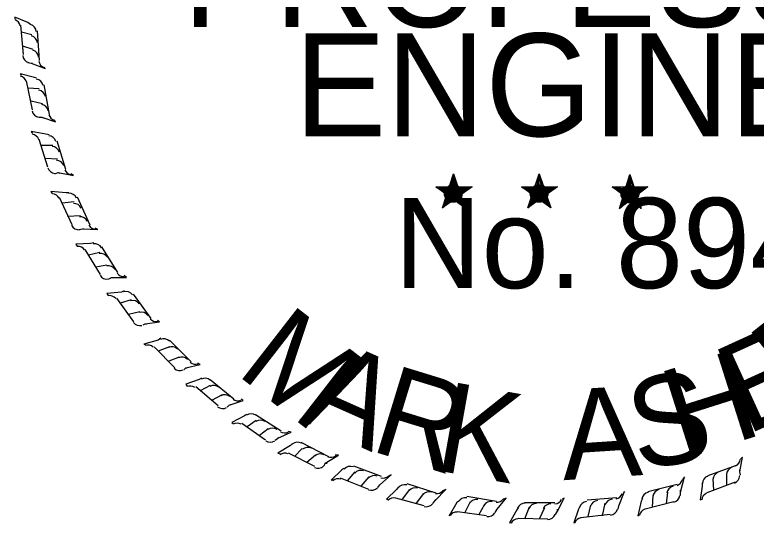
# Model space of a CAD drawing. Extents: x 1369528 to 1373075, y 373809 to 376031.
# Drawn here: x 1372616.4 to 1372751.6, y 373959.4 to 374052.1 of the extents above; entities that cross this region are included whole.
import ezdxf

# ---------------------------------------------------------------- set-up
doc = ezdxf.new("R2010")
doc.units = 0
doc.layers.add('R_Border Notes', color=7, linetype='Continuous')

msp = doc.modelspace()

# ---------------------------------------------------------------- linework, layer by layer
at = {"layer": 'R_Border Notes'}
for p, q in [((1372618.79, 374050.76), (1372616.39, 374051.72)), ((1372616.39, 374051.72), (1372616.39, 374051.36)), ((1372617.95, 374044.88), (1372617.47, 374050.28)), ((1372619.27, 374050.4), (1372618.79, 374050.76)), ((1372619.51, 374048.48), (1372617.59, 374048.96)), ((1372620.47, 374049.2), (1372620.83, 374043.8)), ((1372619.75, 374045.84), (1372617.83, 374046.44)), ((1372618.79, 374043.44), (1372619.39, 374043.32)), ((1372619.39, 374043.32), (1372621.91, 374042.36)), ((1372619.39, 374043.32), (1372619.63, 374043.32)), ((1372621.91, 374042.36), (1372621.79, 374042.6)), ((1372619.99, 374040.68), (1372617.35, 374041.4)), ((1372617.35, 374041.4), (1372617.59, 374041.16)), ((1372620.35, 374040.56), (1372619.99, 374040.68)), ((1372619.63, 374034.8), (1372618.55, 374040.08)), ((1372621.67, 374039.36), (1372622.63, 374033.96)), ((1372620.83, 374038.64), (1372618.79, 374038.76)), ((1372621.43, 374035.88), (1372619.39, 374036.36)), ((1372620.83, 374033.48), (1372621.31, 374033.48)), ((1372621.31, 374033.48), (1372623.83, 374032.64)), ((1372621.31, 374033.48), (1372621.55, 374033.36)), ((1372623.83, 374032.64), (1372623.59, 374033)), ((1372622.03, 374030.36), (1372619.39, 374030.84)), ((1372619.39, 374030.84), (1372619.63, 374030.48)), ((1372622.39, 374024.36), (1372620.83, 374029.4)), ((1372622.63, 374030.24), (1372622.03, 374030.36)), ((1372623.35, 374028.32), (1372621.19, 374028.32)), ((1372624.07, 374029.16), (1372625.63, 374024)), ((1372624.19, 374025.8), (1372621.91, 374025.92)), ((1372623.71, 374023.16), (1372624.31, 374023.4)), ((1372624.31, 374023.4), (1372627.07, 374022.8)), ((1372624.31, 374023.4), (1372624.55, 374023.28)), ((1372627.07, 374022.8), (1372626.59, 374023.16)), ((1372696.43, 374023.16), (1372695.83, 374020.76)), ((1372696.43, 374023.16), (1372696.07, 374020.76)), ((1372696.43, 374023.16), (1372696.19, 374020.76)), ((1372696.43, 374019.68), (1372696.43, 374023.16)), ((1372696.43, 374023.16), (1372697.03, 374020.76)), ((1372696.43, 374023.16), (1372696.91, 374020.76)), ((1372696.43, 374023.16), (1372696.67, 374020.76)), ((1372712.03, 374023.16), (1372711.55, 374020.76)), ((1372712.03, 374023.16), (1372711.79, 374020.76)), ((1372712.03, 374023.16), (1372711.91, 374020.76)), ((1372712.03, 374019.68), (1372712.03, 374023.16)), ((1372712.03, 374023.16), (1372712.63, 374020.76)), ((1372712.03, 374023.16), (1372712.51, 374020.76)), ((1372712.03, 374023.16), (1372712.39, 374020.76)), ((1372728.59, 374023.04), (1372728.11, 374020.76)), ((1372728.59, 374023.04), (1372728.23, 374020.76)), ((1372728.59, 374019.56), (1372728.59, 374023.04)), ((1372728.59, 374023.04), (1372729.19, 374020.76)), ((1372728.59, 374023.04), (1372729.19, 374020.76)), ((1372728.59, 374023.04), (1372728.83, 374020.76)), ((1372728.59, 374023.04), (1372728.59, 374020.76)), ((1372625.75, 374019.68), (1372622.99, 374019.92)), ((1372622.99, 374019.92), (1372623.23, 374019.56)), ((1372693.19, 374020.76), (1372696.43, 374019.68)), ((1372693.19, 374020.76), (1372695.59, 374020.52)), ((1372693.19, 374020.76), (1372695.59, 374020.28)), ((1372693.19, 374020.76), (1372695.47, 374020.16)), ((1372693.19, 374020.76), (1372695.47, 374019.8)), ((1372693.19, 374020.76), (1372695.35, 374019.56)), ((1372693.19, 374020.76), (1372695.35, 374019.44)), ((1372699.79, 374020.76), (1372696.43, 374019.68)), ((1372699.79, 374020.76), (1372696.79, 374020.52)), ((1372699.79, 374020.76), (1372697.03, 374020.28)), ((1372699.79, 374020.76), (1372697.03, 374020.16)), ((1372699.79, 374020.76), (1372697.63, 374019.92)), ((1372699.79, 374020.76), (1372697.75, 374019.8)), ((1372699.79, 374020.76), (1372697.99, 374019.68)), ((1372708.79, 374020.76), (1372712.03, 374019.68)), ((1372708.79, 374020.76), (1372711.19, 374020.52)), ((1372708.79, 374020.76), (1372711.19, 374020.28)), ((1372708.79, 374020.76), (1372711.19, 374020.16)), ((1372708.79, 374020.76), (1372711.07, 374019.8)), ((1372708.79, 374020.76), (1372711.07, 374019.56)), ((1372708.79, 374020.76), (1372711.07, 374019.44)), ((1372715.39, 374020.76), (1372712.03, 374019.68)), ((1372715.39, 374020.76), (1372712.39, 374020.52)), ((1372715.39, 374020.76), (1372712.63, 374020.28)), ((1372715.39, 374020.76), (1372712.63, 374020.16)), ((1372715.39, 374020.76), (1372713.23, 374019.92)), ((1372715.39, 374020.76), (1372713.47, 374019.8)), ((1372715.39, 374020.76), (1372713.59, 374019.68)), ((1372725.35, 374020.76), (1372728.59, 374019.56)), ((1372725.35, 374020.76), (1372727.75, 374020.4)), ((1372725.35, 374020.76), (1372727.75, 374020.16)), ((1372725.35, 374020.76), (1372727.63, 374020.16)), ((1372725.35, 374020.76), (1372727.63, 374019.68)), ((1372725.35, 374020.76), (1372727.63, 374019.56)), ((1372725.35, 374020.76), (1372727.63, 374019.32)), ((1372731.83, 374020.76), (1372728.59, 374019.56)), ((1372731.83, 374020.76), (1372729.07, 374020.4)), ((1372731.83, 374020.76), (1372729.19, 374020.16)), ((1372731.83, 374020.76), (1372729.19, 374020.04)), ((1372731.83, 374020.76), (1372729.79, 374019.8)), ((1372731.83, 374020.76), (1372730.03, 374019.68)), ((1372731.83, 374020.76), (1372730.15, 374019.56)), ((1372626.83, 374013.8), (1372624.55, 374018.84)), ((1372626.23, 374019.68), (1372625.75, 374019.68)), ((1372627.79, 374018.96), (1372630.07, 374013.8)), ((1372694.39, 374016.92), (1372696.43, 374019.68)), ((1372694.39, 374016.92), (1372695.47, 374019.56)), ((1372694.39, 374016.92), (1372695.59, 374019.2)), ((1372694.39, 374016.92), (1372695.71, 374019.08)), ((1372694.39, 374016.92), (1372696.07, 374018.96)), ((1372694.39, 374016.92), (1372696.43, 374018.96)), ((1372694.39, 374016.92), (1372696.43, 374018.72)), ((1372698.47, 374016.92), (1372696.43, 374019.68)), ((1372698.47, 374016.92), (1372696.43, 374018.96)), ((1372698.47, 374016.92), (1372696.43, 374018.6)), ((1372698.47, 374016.92), (1372696.79, 374018.96)), ((1372698.47, 374016.92), (1372697.03, 374019.2)), ((1372698.47, 374016.92), (1372697.15, 374019.56)), ((1372698.47, 374016.92), (1372697.39, 374019.68)), ((1372709.99, 374016.92), (1372712.03, 374019.68)), ((1372709.99, 374016.92), (1372711.19, 374019.56)), ((1372709.99, 374016.92), (1372711.19, 374019.2)), ((1372709.99, 374016.92), (1372711.43, 374019.08)), ((1372709.99, 374016.92), (1372711.79, 374018.96)), ((1372709.99, 374016.92), (1372712.03, 374018.96)), ((1372709.99, 374016.92), (1372712.15, 374018.72)), ((1372714.19, 374016.92), (1372712.03, 374019.68)), ((1372714.19, 374016.92), (1372712.03, 374018.96)), ((1372714.19, 374016.92), (1372712.03, 374018.6)), ((1372714.19, 374016.92), (1372712.39, 374018.96)), ((1372714.19, 374016.92), (1372712.63, 374019.2)), ((1372714.19, 374016.92), (1372712.87, 374019.56)), ((1372714.19, 374016.92), (1372712.99, 374019.68)), ((1372726.67, 374016.8), (1372728.59, 374019.56)), ((1372726.67, 374016.8), (1372727.63, 374019.44)), ((1372726.67, 374016.8), (1372727.87, 374019.08)), ((1372726.67, 374016.8), (1372727.99, 374018.96)), ((1372726.67, 374016.8), (1372728.23, 374018.84)), ((1372726.67, 374016.8), (1372728.59, 374018.84)), ((1372726.67, 374016.8), (1372728.71, 374018.6)), ((1372730.63, 374016.8), (1372728.59, 374019.56)), ((1372730.63, 374016.8), (1372728.59, 374018.84)), ((1372730.63, 374016.8), (1372728.59, 374018.6)), ((1372730.63, 374016.8), (1372729.07, 374018.84)), ((1372730.63, 374016.8), (1372729.31, 374019.56)), ((1372730.63, 374016.8), (1372729.31, 374019.08)), ((1372730.63, 374016.8), (1372729.55, 374019.56)), ((1372627.19, 374018), (1372625.03, 374017.76)), ((1372628.39, 374015.48), (1372625.99, 374015.36)), ((1372628.15, 374012.96), (1372628.75, 374013.08)), ((1372628.75, 374013.08), (1372631.51, 374012.96)), ((1372628.75, 374013.08), (1372628.99, 374013.08)), ((1372631.51, 374012.96), (1372631.03, 374013.2)), ((1372630.19, 374010.44), (1372627.55, 374010.32)), ((1372630.79, 374010.56), (1372630.19, 374010.44)), ((1372627.55, 374010.32), (1372627.79, 374009.96)), ((1372631.99, 374004.8), (1372629.23, 374009.36)), ((1372632.23, 374009.84), (1372635.11, 374005.16)), ((1372631.87, 374008.76), (1372629.83, 374008.28)), ((1372633.19, 374006.48), (1372631.15, 374006.12)), ((1372633.55, 374003.96), (1372634.03, 374004.2)), ((1372634.03, 374004.2), (1372636.79, 374004.2)), ((1372634.03, 374004.2), (1372634.39, 374004.2)), ((1372636.79, 374004.2), (1372636.31, 374004.56)), ((1372635.83, 374001.56), (1372633.19, 374001.32)), ((1372633.19, 374001.32), (1372633.43, 374000.96)), ((1372636.31, 374001.8), (1372635.83, 374001.56)), ((1372637.99, 374001.2), (1372641.23, 373996.76)), ((1372638.11, 373996.16), (1372634.99, 374000.48)), ((1372637.63, 374000.12), (1372635.59, 373999.52)), ((1372639.19, 373997.96), (1372637.15, 373997.48)), ((1372639.79, 373995.56), (1372640.15, 373995.8)), ((1372640.15, 373995.8), (1372642.79, 373996.16)), ((1372640.15, 373995.8), (1372640.39, 373995.8)), ((1372642.79, 373996.16), (1372642.43, 373996.4)), ((1372642.55, 373992.8), (1372639.91, 373992.08)), ((1372643.03, 373993.16), (1372642.55, 373992.8)), ((1372644.59, 373992.8), (1372648.55, 373988.84)), ((1372639.91, 373992.08), (1372640.27, 373991.96)), ((1372645.55, 373987.76), (1372641.83, 373991.6)), ((1372644.59, 373991.6), (1372642.55, 373990.76)), ((1372646.39, 373989.68), (1372644.47, 373988.96)), ((1372647.23, 373987.4), (1372647.59, 373987.76)), ((1372647.59, 373987.76), (1372650.23, 373988.36)), ((1372647.59, 373987.76), (1372647.83, 373987.76)), ((1372650.23, 373988.36), (1372649.75, 373988.6)), ((1372649.99, 373985.6), (1372647.59, 373984.76)), ((1372647.59, 373984.76), (1372647.83, 373984.4)), ((1372650.47, 373985.84), (1372649.99, 373985.6)), ((1372652.03, 373985.6), (1372656.35, 373982.12)), ((1372653.47, 373980.8), (1372649.39, 373984.28)), ((1372652.03, 373984.52), (1372650.23, 373983.56)), ((1372654.19, 373982.84), (1372652.27, 373981.76)), ((1372658.03, 373981.76), (1372657.67, 373982)), ((1372655.15, 373980.56), (1372655.51, 373980.92)), ((1372655.51, 373980.92), (1372658.03, 373981.76)), ((1372655.51, 373980.92), (1372655.75, 373981.04)), ((1372658.27, 373979), (1372655.99, 373977.8)), ((1372658.63, 373979.24), (1372658.27, 373979)), ((1372660.43, 373978.16), (1372658.75, 373976.96)), ((1372660.31, 373979.24), (1372664.99, 373976.24)), ((1372655.99, 373977.8), (1372656.23, 373977.56)), ((1372662.11, 373974.56), (1372657.79, 373977.56)), ((1372662.59, 373976.6), (1372661.03, 373975.4)), ((1372664.39, 373974.92), (1372666.79, 373976)), ((1372666.79, 373976), (1372666.31, 373976.12)), ((1372663.91, 373974.56), (1372664.39, 373974.92)), ((1372664.39, 373974.92), (1372664.51, 373975.04)), ((1372667.03, 373973.96), (1372666.67, 373973.6)), ((1372668.59, 373974.2), (1372673.63, 373971.56)), ((1372666.67, 373973.6), (1372664.39, 373972.16)), ((1372668.83, 373973), (1372667.39, 373971.56)), ((1372664.39, 373972.16), (1372664.87, 373972.04)), ((1372671.11, 373969.76), (1372666.31, 373972.16)), ((1372671.23, 373971.8), (1372669.67, 373970.48)), ((1372673.03, 373970.36), (1372675.43, 373971.8)), ((1372675.43, 373971.8), (1372674.83, 373971.8)), ((1372748.63, 373968.8), (1372749.11, 373971.44)), ((1372749.11, 373971.44), (1372748.75, 373971.08)), ((1372672.79, 373969.88), (1372673.03, 373970.36)), ((1372673.03, 373970.36), (1372673.39, 373970.36)), ((1372678.19, 373969.88), (1372683.23, 373967.96)), ((1372742.87, 373968.08), (1372748.03, 373970)), ((1372676.03, 373969.16), (1372674.11, 373967.24)), ((1372676.39, 373969.4), (1372676.03, 373969.16)), ((1372678.43, 373968.8), (1372676.99, 373967.12)), ((1372748.63, 373968.8), (1372748.63, 373969.16)), ((1372748.75, 373968.2), (1372748.63, 373968.8)), ((1372674.11, 373967.24), (1372674.59, 373967.36)), ((1372680.95, 373965.56), (1372675.79, 373967.6)), ((1372680.95, 373967.84), (1372679.51, 373966.16)), ((1372682.99, 373966.4), (1372685.03, 373968.2)), ((1372685.03, 373968.2), (1372684.55, 373967.96)), ((1372737.83, 373965.08), (1372738.55, 373967.84)), ((1372738.55, 373967.84), (1372738.19, 373967.36)), ((1372743.71, 373967.48), (1372743.83, 373965.44)), ((1372746.23, 373968.44), (1372746.23, 373966.28)), ((1372682.63, 373965.92), (1372682.99, 373966.4)), ((1372682.99, 373966.4), (1372683.11, 373966.52)), ((1372686.35, 373966.04), (1372685.99, 373965.56)), ((1372687.91, 373966.64), (1372693.19, 373964.96)), ((1372731.83, 373965.2), (1372737.23, 373966.52)), ((1372741.79, 373966.16), (1372741.43, 373963.64)), ((1372741.79, 373966.76), (1372741.79, 373966.16)), ((1372747.79, 373966.88), (1372742.63, 373964.96)), ((1372685.99, 373965.56), (1372684.19, 373963.76)), ((1372688.39, 373965.56), (1372687.07, 373963.76)), ((1372690.91, 373964.84), (1372689.59, 373963.04)), ((1372693.07, 373963.52), (1372694.99, 373965.56)), ((1372694.99, 373965.56), (1372694.39, 373965.32)), ((1372726.55, 373962.56), (1372727.63, 373965.2)), ((1372727.63, 373965.2), (1372727.27, 373964.84)), ((1372732.79, 373964.48), (1372732.67, 373962.32)), ((1372735.43, 373965.08), (1372735.19, 373962.92)), ((1372737.83, 373965.08), (1372737.83, 373965.44)), ((1372737.83, 373964.48), (1372737.83, 373965.08)), ((1372684.19, 373963.76), (1372684.43, 373963.76)), ((1372691.03, 373962.56), (1372685.87, 373964)), ((1372692.71, 373963.04), (1372693.07, 373963.52)), ((1372693.07, 373963.52), (1372693.19, 373963.76)), ((1372697.03, 373963.16), (1372695.59, 373960.76)), ((1372697.39, 373963.4), (1372697.03, 373963.16)), ((1372699.43, 373963.28), (1372698.47, 373961.36)), ((1372698.83, 373964.36), (1372704.23, 373963.4)), ((1372704.35, 373961.96), (1372706.03, 373964)), ((1372706.03, 373964), (1372705.55, 373963.76)), ((1372709.39, 373963.16), (1372714.91, 373963.16)), ((1372715.39, 373961.6), (1372716.59, 373964)), ((1372716.59, 373964), (1372716.23, 373963.76)), ((1372720.79, 373963.64), (1372726.19, 373964.12)), ((1372730.63, 373963.4), (1372730.03, 373960.76)), ((1372730.87, 373963.88), (1372730.63, 373963.4)), ((1372736.63, 373963.28), (1372731.35, 373961.96)), ((1372741.43, 373963.64), (1372741.79, 373963.76)), ((1372702.07, 373962.8), (1372700.99, 373960.88)), ((1372703.99, 373961.36), (1372704.35, 373961.96)), ((1372704.35, 373961.96), (1372704.47, 373962.08)), ((1372707.95, 373961.84), (1372706.63, 373959.44)), ((1372708.19, 373962.2), (1372707.95, 373961.84)), ((1372710.23, 373962.32), (1372709.39, 373960.16)), ((1372712.99, 373962.2), (1372712.03, 373960.16)), ((1372715.39, 373961.6), (1372715.39, 373961.96)), ((1372719.23, 373961.96), (1372718.39, 373959.44)), ((1372719.47, 373962.44), (1372719.23, 373961.96)), ((1372721.39, 373962.68), (1372720.91, 373960.64)), ((1372724.03, 373963.04), (1372723.55, 373960.76)), ((1372726.43, 373961.96), (1372726.55, 373962.56)), ((1372726.55, 373962.56), (1372726.67, 373962.8)), ((1372695.59, 373960.76), (1372695.83, 373961)), ((1372702.43, 373960.76), (1372697.15, 373961.48)), ((1372715.03, 373961), (1372715.39, 373961.6)), ((1372724.99, 373961), (1372719.59, 373960.4)), ((1372730.03, 373960.76), (1372730.39, 373961)), ((1372706.63, 373959.44), (1372706.99, 373959.56)), ((1372713.59, 373960.16), (1372708.19, 373960.28)), ((1372718.39, 373959.44), (1372718.63, 373959.56))]:
    msp.add_line(p, q, dxfattribs=at)
for points in [[(1372696.43, 374023.16), (1372698.47, 374016.92), (1372693.19, 374020.76), (1372699.79, 374020.76), (1372694.39, 374016.92), (1372696.43, 374023.16)], [(1372712.03, 374023.16), (1372714.19, 374016.92), (1372708.79, 374020.76), (1372715.39, 374020.76), (1372709.99, 374016.92), (1372712.03, 374023.16)], [(1372728.59, 374023.04), (1372730.63, 374016.8), (1372725.35, 374020.76), (1372731.83, 374020.76), (1372726.67, 374016.8), (1372728.59, 374023.04)]]:
    msp.add_lwpolyline(points, dxfattribs=at)
for centre, radius in [((1372696.37, 374019.56), 1.61), ((1372696.37, 374019.56), 1.46), ((1372696.37, 374019.56), 1.36), ((1372696.37, 374019.56), 1.24), ((1372696.37, 374019.56), 1.09), ((1372696.37, 374019.56), 1.01), ((1372696.37, 374019.56), 0.929), ((1372696.37, 374019.56), 0.8), ((1372696.37, 374019.56), 0.701), ((1372696.37, 374019.56), 0.583), ((1372696.37, 374019.56), 0.464), ((1372696.37, 374019.56), 0.346), ((1372696.37, 374019.56), 0.278), ((1372712.02, 374019.56), 1.61), ((1372712.02, 374019.56), 1.46), ((1372712.02, 374019.56), 1.36), ((1372712.02, 374019.56), 1.24), ((1372712.02, 374019.56), 1.09), ((1372712.02, 374019.56), 1.01), ((1372712.02, 374019.56), 0.929), ((1372712.02, 374019.56), 0.8), ((1372712.02, 374019.56), 0.701), ((1372712.02, 374019.56), 0.583), ((1372712.02, 374019.56), 0.464), ((1372712.02, 374019.56), 0.346), ((1372712.02, 374019.56), 0.278), ((1372728.58, 374019.45), 1.61), ((1372728.58, 374019.45), 1.46), ((1372728.58, 374019.45), 1.36), ((1372728.58, 374019.45), 1.24), ((1372728.58, 374019.45), 1.09), ((1372728.58, 374019.45), 1.01), ((1372728.58, 374019.45), 0.929), ((1372728.58, 374019.45), 0.8), ((1372728.58, 374019.45), 0.701), ((1372728.58, 374019.45), 0.583), ((1372728.58, 374019.45), 0.464), ((1372696.37, 374019.56), 0.135), ((1372712.02, 374019.56), 0.135), ((1372728.58, 374019.45), 0.346), ((1372728.58, 374019.45), 0.278), ((1372728.58, 374019.45), 0.135)]:
    msp.add_circle(centre, radius, dxfattribs=at)
for centre, start, end in [((1372615.89, 374049.88), 9.4933, 68.2812), ((1372618.84, 374048.95), 5.2325, 73.6065), ((1372619.03, 374046.9), 5.2325, 73.6065), ((1372619.26, 374044.27), 5.2325, 73.6065), ((1372619.3, 374044.84), 185.2325, 253.6065), ((1372622.24, 374043.91), 189.4933, 248.2812), ((1372617.06, 374039.55), 15.7912, 74.579), ((1372620.09, 374038.95), 11.5304, 79.9044), ((1372620.51, 374036.94), 11.5304, 79.9044), ((1372621.03, 374034.35), 11.5304, 79.9044), ((1372621, 374034.92), 191.5304, 259.9044), ((1372624.03, 374034.32), 195.7912, 254.579), ((1372619.39, 374028.87), 22.0938, 80.8817), ((1372622.47, 374028.6), 17.8331, 86.207), ((1372623.11, 374026.65), 17.8331, 86.207), ((1372623.91, 374024.13), 17.8331, 86.207), ((1372623.81, 374024.7), 197.8331, 266.207), ((1372626.89, 374024.43), 202.0938, 260.8817), ((1372623.2, 374017.99), 29.1451, 87.9329), ((1372626.29, 374018.1), 24.8843, 93.2583), ((1372627.16, 374016.24), 24.8843, 93.2583), ((1372628.26, 374013.84), 24.8843, 93.2583), ((1372628.1, 374014.39), 204.8843, 273.2583), ((1372631.19, 374014.5), 209.1451, 267.9329), ((1372627.91, 374008.4), 36.0034, 94.7913), ((1372630.96, 374008.88), 31.7427, 100.1166), ((1372632.04, 374007.13), 31.7427, 100.1166), ((1372633.43, 374004.88), 31.7427, 100.1166), ((1372636.25, 374005.89), 216.0034, 274.7913), ((1372633.2, 374005.41), 211.7427, 280.1166), ((1372633.67, 373999.44), 40.9505, 99.7383), ((1372636.67, 374000.18), 36.6897, 105.0637), ((1372637.9, 373998.54), 36.6897, 105.0637), ((1372639.47, 373996.41), 36.6897, 105.0637), ((1372639.2, 373996.92), 216.6897, 285.0637), ((1372642.2, 373997.66), 220.9505, 279.7383), ((1372643.54, 373991.57), 44.9655, 113.3394), ((1372640.67, 373990.4), 49.2262, 108.0141), ((1372644.99, 373990.12), 44.9655, 113.3394), ((1372646.85, 373988.24), 44.9655, 113.3394), ((1372649.37, 373989.87), 229.2262, 288.0141), ((1372646.51, 373988.71), 224.9655, 293.3394), ((1372651.09, 373984.37), 50.1902, 118.5642), ((1372648.35, 373982.95), 54.451, 113.2388), ((1372652.67, 373983.06), 50.1902, 118.5642), ((1372654.7, 373981.36), 50.1902, 118.5642), ((1372657.06, 373983.21), 234.451, 293.2388), ((1372654.32, 373981.79), 230.1902, 298.5642), ((1372659.5, 373977.88), 56.1736, 124.5476), ((1372661.21, 373976.74), 56.1736, 124.5476), ((1372656.92, 373976.18), 60.4344, 119.2222), ((1372663.4, 373975.26), 56.1736, 124.5476), ((1372665.56, 373977.35), 240.4344, 299.2222), ((1372662.98, 373975.65), 236.1736, 304.5476), ((1372667.99, 373972.69), 63.0708, 131.4448), ((1372669.82, 373971.77), 63.0708, 131.4448), ((1372665.63, 373970.7), 67.3316, 126.1194), ((1372672.17, 373970.56), 63.0708, 131.4448), ((1372674.06, 373972.89), 247.3316, 306.1194), ((1372747.26, 373971.2), 294.7331, 353.521), ((1372671.7, 373970.9), 243.0708, 311.4448), ((1372677.56, 373968.28), 69.0955, 137.4695), ((1372679.48, 373967.55), 69.0955, 137.4695), ((1372745.22, 373967.32), 110.4724, 178.8463), ((1372747.7, 373968.23), 110.4724, 178.8463), ((1372675.42, 373966.04), 73.3563, 132.1441), ((1372681.95, 373966.6), 69.0955, 137.4695), ((1372683.58, 373969.11), 253.3563, 312.1441), ((1372736.72, 373967.71), 288.1674, 346.9552), ((1372743.3, 373966.6), 110.4724, 178.8463), ((1372747.13, 373968.11), 290.4724, 358.8463), ((1372681.44, 373966.88), 249.0955, 317.4695), ((1372687.47, 373964.95), 73.9909, 142.3649), ((1372689.45, 373964.39), 73.9909, 142.3649), ((1372736.81, 373964.71), 103.9066, 172.2806), ((1372691.99, 373963.65), 73.9909, 142.3649), ((1372693.4, 373966.3), 258.2517, 317.0395), ((1372725.81, 373965.32), 279.9249, 338.7128), ((1372732.25, 373963.59), 103.9066, 172.2806), ((1372734.24, 373964.09), 103.9066, 172.2806), ((1372736.24, 373964.66), 283.9066, 352.2806), ((1372743.17, 373963.51), 114.7331, 173.521), ((1372685.53, 373962.54), 78.2517, 137.0395), ((1372698.6, 373962.59), 81.4231, 149.797), ((1372700.63, 373962.29), 81.4231, 149.797), ((1372703.24, 373961.89), 81.4231, 149.797), ((1372704.3, 373964.7), 265.6839, 324.4717), ((1372714.83, 373964.4), 273.4236, 332.2115), ((1372720.8, 373961.87), 95.6641, 164.0381), ((1372722.84, 373962.08), 95.6641, 164.0381), ((1372725.48, 373962.33), 95.6641, 164.0381), ((1372691.46, 373963.89), 253.9909, 322.3649), ((1372709.47, 373961.55), 89.1628, 157.5368), ((1372711.52, 373961.52), 89.1628, 157.5368), ((1372714.16, 373961.48), 89.1628, 157.5368), ((1372724.9, 373962.36), 275.6641, 344.0381), ((1372731.77, 373960.53), 108.1674, 166.9552), ((1372696.99, 373959.96), 85.6839, 144.4717), ((1372702.69, 373962.06), 261.4231, 329.797), ((1372713.59, 373961.57), 269.1628, 337.5368), ((1372719.89, 373958.92), 99.9249, 158.7128), ((1372708.23, 373958.72), 93.4236, 152.2115)]:
    msp.add_arc(centre, 1.48, start, end, dxfattribs=at)

# ---------------------------------------------------------------- texts
for s, height, p in [('PROFESSIONAL', 18.7488, (1372646.99, 374049.92)), ('ENGINEER', 18.749, (1372667.39, 374030)), ('No. 8940', 16.471, (1372685.63, 374002.28))]:
    msp.add_text(s, height=height, dxfattribs=at).set_placement(p)
for s, height, rotation, p in [('R', 16.41, 38.3946, (1372759.55, 373980.2)), ('M', 16.41, 322.1623, (1372656.47, 373986.8)), ('E', 16.41, 24.5342, (1372749.83, 373975.4)), ('A', 16.41, 336.0227, (1372668.23, 373978.28)), ('H', 16.4, 17.604, (1372738.07, 373970.96)), ('R', 16.41, 342.9529, (1372680.83, 373972.76)), ('S', 16.41, 10.6738, (1372730.03, 373968.92)), ('K', 16.41, 349.8831, (1372692.59, 373969.16)), ('A', 16.41, 3.7436, (1372716.47, 373967.24))]:
    msp.add_text(s, height=height, rotation=rotation, dxfattribs=at).set_placement(p)

doc.saveas('drawing.dxf')
